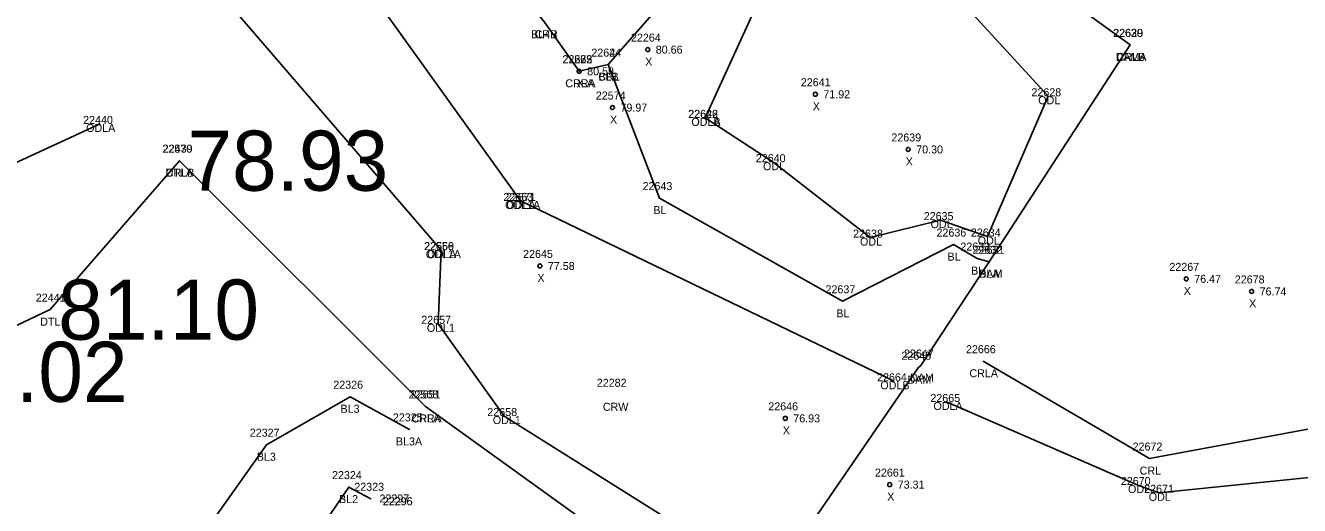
# Model space of a CAD drawing. Extents: x 2266664 to 2272385, y 716533 to 724777.
# Drawn here: x 2271014.2 to 2271173.4, y 722898.9 to 722958.8 of the extents above; entities that cross this region are included whole.
import ezdxf

# ---------------------------------------------------------------- set-up
doc = ezdxf.new("R2010")
doc.units = 0
for name, color, linetype in [('RD_DTM_BkLn1', 7, 'Continuous'), ('RD_EX_Conc_txCode', 7, 'Continuous'), ('RD_EX_Dam', 7, 'Continuous'), ('RD_EX_Dam_txCode', 7, 'Continuous'), ('RD_EX_DR_Inlet_txCode', 7, 'Continuous'), ('RD_EX_H2O', 7, 'Continuous'), ('RD_EX_H2O_txCode', 7, 'Continuous'), ('RD_EX_Road_txCode', 7, 'Continuous'), ('RD_Sketch8', 7, 'Continuous'), ('RD_SMD_Locator', 7, 'Continuous'), ('RD_SMD_Misc', 7, 'Continuous')]:
    doc.layers.add(name, color=color, linetype=linetype)

msp = doc.modelspace()

# ---------------------------------------------------------------- linework, layer by layer
at = {"layer": 'RD_DTM_BkLn1'}
for points in [[(2271134.6, 722929.34), (2271133.09, 722929.74), (2271130.13, 722931.49), (2271116.25, 722924.41), (2271093.38, 722937.29), (2271086.99, 722953.95)], [(2271062.16, 722908.42), (2271054.75, 722912.5), (2271044.28, 722906.51), (2271019.61, 722871.71)], [(2271057.34, 722899.76), (2271054.56, 722901.22), (2271032.9, 722869.52), (2271024.4, 722869.4), (2271019.61, 722871.71)]]:
    msp.add_lwpolyline(points, dxfattribs=at)
at = {"layer": 'RD_EX_Dam'}
msp.add_lwpolyline([(2271152.21, 722956.41), (2271134.6, 722929.34), (2271126.04, 722916.39), (2271125.72, 722916.12), (2271108.94, 722891.69), (2271108.71, 722891.59), (2271102.6, 722882.8)], dxfattribs=at)
at = {"layer": 'RD_EX_H2O'}
for p, q in [((2271064.14, 722911.29), (2271033.41, 722941.96)), ((2271076.01, 722936.94), (2271122.71, 722914.43))]:
    msp.add_line(p, q, dxfattribs=at)
for points in [[(2271083.36, 722953.12), (2271079.03, 722959.24), (2271058.65, 722984.8), (2271040.68, 723020.65), (2271013.48, 723061.78), (2270985.21, 723129.14), (2270950.14, 723216.08), (2270917.35, 723303.24), (2270895.25, 723364.78)], [(2271076.01, 722936.94), (2271050.23, 722972.85), (2271034.32, 723016.83), (2271009.34, 723057.27), (2270980.42, 723125.22), (2270946.35, 723214.21), (2270913.15, 723300.5), (2270891.17, 723363.41)], [(2271066.1, 722930.8), (2271021.57, 722982.52), (2270994.92, 723049.52), (2270960.85, 723124.25), (2270937.66, 723128.7), (2270907.29, 723212.11), (2270880.14, 723282.94), (2270854.62, 723351.46)], [(2271083.36, 722953.12), (2271086.99, 722953.95), (2271113.65, 722984.3), (2271152.21, 722956.41)], [(2271099.11, 722947.3), (2271114.2, 722980.24), (2271141.97, 722950), (2271134.4, 722932.49), (2271128.51, 722934.54), (2271119.7, 722932.36), (2271107.58, 722941.77), (2271099.11, 722947.3)], [(2271023.5, 722946.55), (2270983.34, 722928.04), (2270948.77, 722885.81), (2270936.01, 722854.96), (2270907.81, 722767.63), (2270849.93, 722675.41), (2270794.17, 722593.77), (2270730.31, 722507.93), (2270678, 722428.57), (2270622.95, 722348.52), (2270567.11, 722264.74), (2270510.62, 722184.83), (2270454.97, 722112.23), (2270398.62, 722023.73), (2270335.52, 721936.71), (2270280.46, 721850.25), (2270222.76, 721771.51), (2270169.39, 721696.38), (2270111.35, 721612), (2270050.32, 721526.8), (2269987.94, 721437.31), (2269982.52, 721401.11), (2269986.76, 721385.77), (2270012.24, 721386.18)], [(2271033.41, 722941.96), (2271017.26, 722923.37), (2271000.84, 722915.61), (2270984.69, 722924.7), (2270953.1, 722884.21), (2270916.86, 722756.99), (2270859.77, 722671.98), (2270798.36, 722591.12), (2270738.02, 722501.89), (2270682.59, 722424.89), (2270629.35, 722346.56), (2270572.53, 722262.27), (2270515.87, 722180.88), (2270459.66, 722106.47), (2270403.98, 722020.3), (2270343.58, 721932.89), (2270284.34, 721846.17), (2270230.48, 721766.75), (2270175.19, 721692.18), (2270115.51, 721607.69), (2270056.41, 721522.72), (2269992.94, 721435.27), (2269987.18, 721402.63)], [(2271066.1, 722930.8), (2271065.74, 722921.6), (2271073.98, 722910.09), (2271095.87, 722896.35), (2271110.14, 722895.51)], [(2271133.84, 722916.93), (2271154.62, 722904.78), (2271177.12, 722908.95)], [(2271064.14, 722911.29), (2271095.29, 722888.89), (2271102.6, 722882.8), (2271117.86, 722885), (2271133.88, 722877.53), (2271131.49, 722848.3), (2271161.12, 722800.68), (2271158.38, 722790.92), (2271209.97, 722733.05), (2271257.97, 722699.07), (2271328.71, 722663.53), (2271328.76, 722676.23), (2271359.03, 722679.94), (2271405.02, 722657.62), (2271442.98, 722642.77), (2271440.33, 722616.88), (2271427.19, 722613.92), (2271489.22, 722575.87)], [(2271129.36, 722911.84), (2271153.18, 722901.48), (2271155.78, 722900.51), (2271177.85, 722902.74), (2271201.84, 722887.34), (2271215.1, 722884.79), (2271219.95, 722858.82), (2271232.72, 722821.83), (2271249.45, 722774.17), (2271246.55, 722773.42), (2271242.67, 722777.55), (2271238.21, 722784.89), (2271226, 722791.87), (2271212.02, 722807.07), (2271179.99, 722825.53), (2271166.96, 722821.86), (2271183.23, 722802.58), (2271216.87, 722768.55), (2271264.5, 722731.34), (2271320.51, 722707.37), (2271341.1, 722714.58), (2271416.82, 722677.3), (2271508.46, 722629.61)]]:
    msp.add_lwpolyline(points, dxfattribs=at)
at = {"layer": 'RD_SMD_Locator'}
for centre, radius in [((2271091.93, 722955.82), 0.25), ((2271152.21, 722956.41), 0.001), ((2271152.21, 722956.41), 0.001), ((2271086.99, 722953.95), 0.001), ((2271086.99, 722953.95), 0.001), ((2271083.36, 722953.12), 0.25), ((2271083.36, 722953.12), 0.001), ((2271083.36, 722953.12), 0.001), ((2271112.87, 722950.25), 0.25), ((2271141.97, 722950), 0.001), ((2271087.52, 722948.59), 0.25), ((2271023.5, 722946.55), 0.001), ((2271099.11, 722947.3), 0.001), ((2271099.11, 722947.3), 0.001), ((2271124.47, 722943.36), 0.25), ((2271033.41, 722941.96), 0.001), ((2271033.41, 722941.96), 0.001), ((2271107.58, 722941.77), 0.001), ((2271076.01, 722936.94), 0.001), ((2271076.01, 722936.94), 0.001), ((2271093.38, 722937.29), 0.001), ((2271128.51, 722934.54), 0.001), ((2271119.7, 722932.36), 0.001), ((2271130.13, 722931.49), 0.001), ((2271134.4, 722932.49), 0.001), ((2271066.1, 722930.8), 0.001), ((2271066.1, 722930.8), 0.001), ((2271078.45, 722928.82), 0.25), ((2271133.09, 722929.74), 0.001), ((2271134.6, 722929.34), 0.001), ((2271134.6, 722929.34), 0.001), ((2271159.21, 722927.21), 0.25), ((2271167.38, 722925.64), 0.25), ((2271116.25, 722924.41), 0.001), ((2271017.26, 722923.37), 0.001), ((2271065.74, 722921.6), 0.001), ((2271125.72, 722916.12), 0.001), ((2271126.04, 722916.39), 0.001), ((2271133.84, 722916.93), 0.001), ((2271122.71, 722914.43), 0.001), ((2271054.75, 722912.5), 0.001), ((2271064.14, 722911.29), 0.001), ((2271064.14, 722911.29), 0.001), ((2271129.36, 722911.84), 0.001), ((2271073.98, 722910.09), 0.001), ((2271109.11, 722909.8), 0.25), ((2271062.16, 722908.42), 0.001), ((2271044.28, 722906.51), 0.001), ((2271154.62, 722904.78), 0.001), ((2271054.56, 722901.22), 0.001), ((2271122.16, 722901.53), 0.25), ((2271153.18, 722901.48), 0.001), ((2271057.34, 722899.76), 0.001), ((2271155.78, 722900.51), 0.001)]:
    msp.add_circle(centre, radius, dxfattribs=at)

# ---------------------------------------------------------------- texts
at = {"layer": 'RD_EX_Conc_txCode'}
msp.add_text('22296', height=1, dxfattribs=at).set_placement((2271058.81, 722898.95))
at = {"layer": 'RD_EX_Dam_txCode'}
for s, p in [('22630', (2271150.06, 722957.41)), ('DAMA', (2271150.39, 722954.41)), ('22631', (2271132.78, 722930.34)), ('DAM', (2271133.27, 722927.34)), ('22648', (2271123.62, 722917.12)), ('22647', (2271123.94, 722917.39)), ('DAM', (2271124.39, 722914.12)), ('DAM', (2271124.71, 722914.39))]:
    msp.add_text(s, height=1, dxfattribs=at).set_placement(p)
at = {"layer": 'RD_EX_DR_Inlet_txCode'}
for s, p in [('78.93', (2271034.41, 722938.21)), ('81.10', (2271018.26, 722919.62)), ('81.02', (2271001.84, 722911.86))]:
    msp.add_text(s, height=7.5, dxfattribs=at).set_placement(p)
at = {"layer": 'RD_EX_H2O_txCode'}
for s, p in [('CRR', (2271077.78, 722957.24)), ('22629', (2271150.1, 722957.41)), ('22624', (2271084.88, 722954.95)), ('CRLB', (2271150.51, 722954.41)), ('22623', (2271081.26, 722954.12)), ('22572', (2271081.28, 722954.12)), ('CRRA', (2271081.62, 722951.12)), ('CRLA', (2271081.64, 722951.12)), ('CRL', (2271085.76, 722951.95)), ('22628', (2271139.87, 722950)), ('ODL', (2271140.72, 722949)), ('22440', (2271021.38, 722946.55)), ('22626', (2271096.98, 722947.3)), ('22642', (2271097, 722947.3)), ('ODLA', (2271021.76, 722945.55)), ('ODLA', (2271097.37, 722946.3)), ('ODLB', (2271097.39, 722946.3)), ('22570', (2271031.29, 722942.96)), ('22439', (2271031.33, 722942.96)), ('22640', (2271105.43, 722941.77)), ('CRLB', (2271031.71, 722939.96)), ('DTLA', (2271031.68, 722939.96)), ('ODL', (2271106.33, 722940.77)), ('22663', (2271073.88, 722936.94)), ('22571', (2271074.21, 722936.94)), ('ODL1A', (2271074.11, 722935.94)), ('ODLA', (2271074.27, 722935.94)), ('22635', (2271126.41, 722934.54)), ('22638', (2271117.59, 722932.36)), ('ODL', (2271127.27, 722933.54)), ('22634', (2271132.3, 722932.49)), ('22656', (2271063.97, 722930.8)), ('22569', (2271064, 722930.8)), ('ODL', (2271118.45, 722931.36)), ('ODL', (2271133.16, 722931.49)), ('ODL1A', (2271064.2, 722929.8)), ('ODLA', (2271064.37, 722929.8)), ('22441', (2271015.47, 722924.37)), ('DTL', (2271016.02, 722921.37)), ('22657', (2271063.63, 722921.6)), ('ODL1', (2271064.33, 722920.6)), ('22666', (2271131.69, 722917.93)), ('CRLA', (2271132.12, 722914.93)), ('22664', (2271120.58, 722914.43)), ('ODLB', (2271120.99, 722913.43)), ('22568', (2271062.04, 722912.29)), ('22651', (2271062.32, 722912.29)), ('22665', (2271127.24, 722911.84)), ('22658', (2271071.88, 722910.09)), ('ODLA', (2271127.63, 722910.84)), ('CRRA', (2271062.4, 722909.29)), ('CRLA', (2271062.43, 722909.29)), ('ODL1', (2271072.57, 722909.09)), ('22672', (2271152.51, 722905.78)), ('CRL', (2271153.39, 722902.78)), ('22670', (2271151.04, 722901.48)), ('ODL', (2271151.94, 722900.48)), ('22671', (2271153.96, 722900.51)), ('ODL', (2271154.53, 722899.51))]:
    msp.add_text(s, height=1, dxfattribs=at).set_placement(p)
at = {"layer": 'RD_EX_Road_txCode'}
msp.add_text('22295', height=1, dxfattribs=at).set_placement((2271058.84, 722898.95))
at = {"layer": 'RD_Sketch8'}
for s, p in [('22264', (2271089.83, 722956.82)), ('80.66', (2271092.93, 722955.32)), ('22265', (2271081.26, 722954.12)), ('X', (2271091.61, 722953.82)), ('X', (2271083.04, 722951.12)), ('80.59', (2271084.36, 722952.62)), ('22641', (2271111.05, 722951.25)), ('22574', (2271085.44, 722949.59)), ('71.92', (2271113.87, 722949.75)), ('79.97', (2271088.52, 722948.09)), ('X', (2271112.55, 722948.25)), ('X', (2271087.21, 722946.59)), ('22639', (2271122.37, 722944.36)), ('70.30', (2271125.47, 722942.86)), ('X', (2271124.16, 722941.36)), ('22645', (2271076.35, 722929.82)), ('77.58', (2271079.45, 722928.32)), ('22267', (2271157.11, 722928.21)), ('X', (2271078.14, 722926.82)), ('76.47', (2271160.21, 722926.71)), ('22678', (2271165.28, 722926.64)), ('X', (2271158.9, 722925.21)), ('76.74', (2271168.38, 722925.14)), ('X', (2271167.07, 722923.64)), ('22646', (2271106.99, 722910.8)), ('76.93', (2271110.11, 722909.3)), ('X', (2271108.8, 722907.8)), ('22661', (2271120.32, 722902.53)), ('73.31', (2271123.16, 722901.03)), ('X', (2271121.85, 722899.53))]:
    msp.add_text(s, height=1, dxfattribs=at).set_placement(p)
at = {"layer": 'RD_SMD_Misc'}
for s, p in [('BL4B', (2271077.35, 722957.24)), ('22644', (2271084.88, 722954.95)), ('BLB', (2271085.76, 722951.95)), ('22643', (2271091.28, 722938.29)), ('BL', (2271092.63, 722935.29)), ('22636', (2271128.01, 722932.49)), ('22633', (2271130.99, 722930.74)), ('BL', (2271129.38, 722929.49)), ('22632', (2271132.5, 722930.34)), ('BL', (2271132.33, 722927.74)), ('BLA', (2271133.36, 722927.34)), ('22637', (2271114.14, 722925.41)), ('BL', (2271115.49, 722922.41)), ('22326', (2271052.64, 722913.5)), ('22282', (2271085.56, 722913.74)), ('BL3', (2271053.54, 722910.5)), ('CRW', (2271086.32, 722910.74)), ('22325', (2271060.08, 722909.42)), ('22327', (2271042.2, 722907.51)), ('BL3A', (2271060.46, 722906.42)), ('BL3', (2271043.08, 722904.51)), ('22324', (2271052.48, 722902.22)), ('22323', (2271055.26, 722900.76)), ('BL2', (2271053.35, 722899.22)), ('22297', (2271058.4, 722899.3))]:
    msp.add_text(s, height=1, dxfattribs=at).set_placement(p)

doc.saveas('drawing.dxf')
